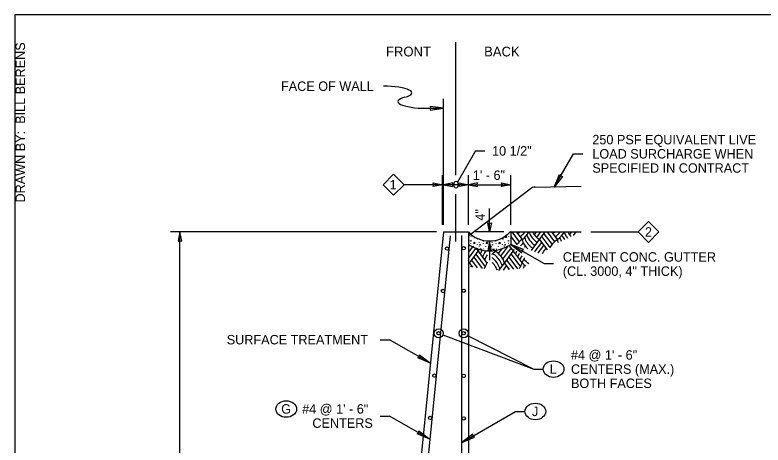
# Model space of a CAD drawing. Extents: x 99862 to 103151, y 100000 to 105076.
# Drawn here: x 99862 to 101127, y 101348 to 102076 of the extents above; entities that cross this region are included whole.
import ezdxf

# ---------------------------------------------------------------- set-up
doc = ezdxf.new("R2010")
doc.units = 0
for name, color, linetype in [('Level 1', 7, 'Continuous'), ('Level 10', 7, 'Continuous'), ('Level 13', 7, 'Continuous'), ('Level 15', 7, 'Continuous'), ('Level 2', 7, 'Continuous'), ('Level 20', 7, 'Continuous'), ('Level 22', 7, 'Continuous'), ('Level 5', 7, 'Continuous'), ('Level 62', 7, 'Continuous')]:
    doc.layers.add(name, color=color, linetype=linetype)

msp = doc.modelspace()

# ---------------------------------------------------------------- linework, layer by layer
at = {"layer": 'Level 1'}
msp.add_lwpolyline([(99862, 99999.5), (103151, 99999.5), (103151, 102075.5), (99862, 102075.5)], close=True, dxfattribs=at)
at = {"layer": 'Level 10'}
for p, q in [((100586.9, 101708.3), (100495.4, 100796.3)), ((100586.9, 101708.3), (100628.9, 101708.3)), ((100628.9, 101708.3), (100628.9, 100796.3)), ((100633.6, 101700.1), (100633.8, 101700.5)), ((100639.2, 101697.2), (100639.3, 101697)), ((100697.4, 101700.1), (100697.6, 101700.5)), ((100700.9, 101707.3), (100700.9, 101687.2)), ((100633.2, 101688.8), (100633.3, 101689.2)), ((100643.7, 101687.7), (100643.8, 101687.3)), ((100647.7, 101690.6), (100647.9, 101691)), ((100654.4, 101688.8), (100654.6, 101689.2)), ((100665, 101687.7), (100665, 101687.3)), ((100669, 101690.6), (100669.1, 101691)), ((100675.7, 101688.8), (100675.9, 101689.2)), ((100686.3, 101687.7), (100686.3, 101687.3)), ((100690.2, 101690.6), (100690.4, 101691)), ((100697, 101688.8), (100697.2, 101689.2)), ((100637.2, 101683.6), (100637.4, 101684)), ((100644.1, 101680.4), (100644.3, 101680.8)), ((100646.8, 101683.6), (100646.9, 101683.4)), ((100646.9, 101683.5), (100647.1, 101683.3)), ((100654.9, 101679.3), (100655.1, 101679.7)), ((100658.5, 101683.6), (100658.7, 101684)), ((100660.4, 101676.5), (100660.5, 101676.4)), ((100665.4, 101680.4), (100665.6, 101680.8)), ((100668, 101683.6), (100668.2, 101683.4)), ((100668.2, 101683.5), (100668.4, 101683.3)), ((100676.1, 101679.3), (100676.3, 101679.7)), ((100679.7, 101683.6), (100679.9, 101684)), ((100686.7, 101680.4), (100686.8, 101680.8)), ((100689.3, 101683.6), (100689.5, 101683.4)), ((100689.5, 101683.5), (100689.6, 101683.3))]:
    msp.add_line(p, q, dxfattribs=at)
for points in [[(100686.4, 101696.1), (100686.9, 101697.2), (100687.8, 101696.5), (100686.4, 101696.1)], [(100691.4, 101698.9), (100692.5, 101700.9)], [(100692.7, 101701), (100693.6, 101699.1), (100691.5, 101698.9)], [(100632.3, 101692.9), (100632.8, 101694), (100633.7, 101693.3), (100632.3, 101692.9)], [(100638.6, 101688.3), (100638.9, 101690.9), (100640.5, 101689.2), (100638.6, 101688.4)], [(100643.8, 101696.1), (100644.2, 101696.9)], [(100645.1, 101696.5), (100643.8, 101696.1)], [(100647.8, 101686), (100648.3, 101687.1), (100649.2, 101686.4), (100647.8, 101686)], [(100654.7, 101693.5), (100655, 101693.3), (100653.6, 101692.9)], [(100653.6, 101692.9), (100653.9, 101693.5)], [(100659.8, 101688.3), (100660.2, 101690.9), (100661.8, 101689.2), (100659.9, 101688.4)], [(100669, 101686), (100669.6, 101687.1), (100670.5, 101686.4), (100669, 101686)], [(100676, 101693.5), (100676.2, 101693.3), (100674.8, 101692.9)], [(100674.8, 101692.9), (100675, 101693.3)], [(100681.1, 101688.3), (100681.5, 101690.9), (100683, 101689.2), (100681.1, 101688.4)], [(100690.3, 101686), (100690.8, 101687.1), (100691.7, 101686.4), (100690.3, 101686)], [(100696.1, 101692.9), (100696.6, 101694), (100697.5, 101693.3), (100696.1, 101692.9)], [(100649, 101678.4), (100650.1, 101680.4), (100651, 101678.3), (100649.5, 101678.2)], [(100670.2, 101678.1), (100671.4, 101680.4), (100672.3, 101678.3), (100670.2, 101678.1)]]:
    msp.add_lwpolyline(points, dxfattribs=at)
for centre, radius, start, end in [((100664.2, 101741.5), 48.5, 223.301, 316.2231), ((100699.9, 101707.3), 1, 0, 134.9971), ((100664.9, 101740.8), 64.5, 236.0728, 303.9272)]:
    msp.add_arc(centre, radius, start, end, dxfattribs=at)
at = {"layer": 'Level 13'}
for p, q in [((100598.2, 101701.7), (100517.4, 100896.3)), ((100618, 100957.3), (100618, 101702.3))]:
    msp.add_line(p, q, dxfattribs=at)
at = {"layer": 'Level 15'}
for p, q in [((100607.9, 101804.3), (100607.9, 102029.5)), ((100586.9, 101720.3), (100586.9, 101933.5)), ((100558, 101917.5), (100586.9, 101917.5)), ((100641, 101845.5), (100610.3, 101792.5)), ((100641, 101845.5), (100657, 101845.5)), ((100774, 101784.1), (100806.5, 101840.4)), ((100806.5, 101840.4), (100822.5, 101840.4)), ((100584.9, 101720.3), (100584.9, 101804.3)), ((100628.9, 101720.3), (100628.9, 101804.3)), ((100700.9, 101720.3), (100700.9, 101804.3)), ((100584.9, 101788.3), (100520.1, 101788.3)), ((100628.9, 101788.3), (100586.9, 101788.3)), ((100628.9, 101788.3), (100700.9, 101788.3)), ((100607.9, 101692.3), (100607.9, 101772.3)), ((100664.9, 101708.3), (100664.9, 101747.9)), ((100574.9, 101708.3), (100124.9, 101708.3)), ((100140.9, 101220.3), (100140.9, 101708.3)), ((100688.9, 101708.3), (100640.9, 101708.3)), ((100836, 101708.3), (100916, 101708.3)), ((100664.9, 101692.3), (100664.9, 101660.3)), ((100700.9, 101687.2), (100757.2, 101654.7)), ((100757.2, 101654.7), (100773.2, 101654.7)), ((100585.6, 101534.2), (100739.5, 101476.2)), ((100627.7, 101533.3), (100739.5, 101476.2)), ((100479.8, 101526), (100495.8, 101526)), ((100564.6, 101486.2), (100495.8, 101526)), ((100739.5, 101476.2), (100755.5, 101476.2)), ((100479.8, 101396.7), (100495.8, 101396.7)), ((100563.6, 101357.5), (100495.8, 101396.7)), ((100618, 101352.1), (100708.7, 101404.5)), ((100708.7, 101404.5), (100724.7, 101404.5))]:
    msp.add_line(p, q, dxfattribs=at)
for points in [[(100586.9, 101917.5), (100564.1, 101920.5), (100565.1, 101917.5), (100564.1, 101914.6)], [(100774, 101784.1), (100782.9, 101805.4), (100784.9, 101803), (100788, 101802.4)], [(100584.9, 101788.3), (100569.2, 101785.2), (100569.9, 101788.3), (100569.2, 101791.3)], [(100586.9, 101788.3), (100602.6, 101785.2), (100601.9, 101788.3), (100602.6, 101791.3)], [(100628.9, 101788.3), (100613.2, 101785.2), (100613.9, 101788.3), (100613.2, 101791.3)], [(100628.9, 101788.3), (100644.6, 101785.2), (100643.9, 101788.3), (100644.6, 101791.3)], [(100700.9, 101788.3), (100685.2, 101785.2), (100685.9, 101788.3), (100685.2, 101791.3)], [(100664.9, 101708.3), (100661.8, 101724), (100664.9, 101723.3), (100668, 101724)], [(100140.9, 101708.3), (100137.8, 101692.5), (100140.9, 101693.3), (100144, 101692.5)], [(100664.9, 101692.3), (100661.8, 101676.5), (100664.9, 101677.3), (100668, 101676.5)], [(100700.9, 101687.2), (100719.2, 101673.2), (100719.7, 101676.3), (100722.1, 101678.4)], [(100564.6, 101486.2), (100543.3, 101495.1), (100545.8, 101497.1), (100546.3, 101500.2)], [(100563.6, 101357.5), (100542.4, 101366.4), (100544.8, 101368.4), (100545.4, 101371.5)], [(100618, 101352.1), (100639.3, 101361), (100636.9, 101363), (100636.3, 101366.1)]]:
    msp.add_lwpolyline(points, close=True, dxfattribs=at)
for centre in [(100578.6, 101536.8), (100621, 101536.8)]:
    msp.add_circle(centre, 7.5, dxfattribs=at)
for centre, start_param, end_param in [((100485.2, 101943.7), 5.569461, 7.853982), ((100558, 101928.9), 2.427868, 4.712389)]:
    msp.add_ellipse(centre, major_axis=(48.2, 0), ratio=0.234933, start_param=start_param, end_param=end_param, dxfattribs=at)
msp.add_ellipse((100607.9, 101788.3), major_axis=(0, -6), ratio=0.57735, dxfattribs=at)
at = {"layer": 'Level 2'}
for p, q in [((100699.9, 101708.3), (100820, 101708.3)), ((100700.9, 101700.6), (100711, 101687.1)), ((100702.6, 101708.3), (100715, 101691.6)), ((100710, 101708.3), (100719.7, 101695.3)), ((100740.7, 101703.4), (100744.3, 101708.3)), ((100744.7, 101699), (100751.7, 101708.3)), ((100749.4, 101695.3), (100759.1, 101708.3)), ((100753.1, 101700.2), (100766.9, 101681.8)), ((100756.8, 101705.2), (100770.4, 101687.1)), ((100762, 101708.3), (100774.4, 101691.6)), ((100769.4, 101708.3), (100779.1, 101695.3)), ((100800.1, 101703.4), (100803.7, 101708.3)), ((100806.5, 101702.1), (100811.1, 101708.3)), ((100817.7, 101707.2), (100818.5, 101708.3)), ((100628.9, 101683.1), (100631, 101685.9)), ((100690, 101675.5), (100697, 101684.8)), ((100735.8, 101677.1), (100749.4, 101695.3)), ((100742, 101675.5), (100753.1, 101690.3)), ((100749.4, 101695.3), (100762.2, 101678.2)), ((100749.4, 101675.5), (100756.8, 101685.4)), ((100628.9, 101673.2), (100630.6, 101675.5)), ((100628.9, 101663.3), (100638, 101675.5)), ((100630.6, 101675.5), (100636.4, 101683.2)), ((100630.6, 101655.7), (100645.5, 101675.5)), ((100638, 101675.5), (100641.7, 101680.4)), ((100641, 101681.5), (100645.5, 101675.5)), ((100645.5, 101675.5), (100660.3, 101655.7)), ((100675.2, 101675.5), (100677, 101678)), ((100679.8, 101671.8), (100682.6, 101675.5)), ((100682.6, 101675.5), (100685.9, 101679.9)), ((100683.9, 101667.3), (100690, 101675.5)), ((100687.3, 101662), (100697.4, 101675.5)), ((100690, 101655.7), (100704.9, 101675.5)), ((100697.4, 101675.5), (100701.1, 101680.4)), ((100698.4, 101684.1), (100704.9, 101675.5)), ((100704.9, 101675.5), (100719.7, 101655.7)), ((100741.4, 101674.7), (100742, 101675.5)), ((100747.1, 101672.4), (100749.4, 101675.5)), ((100754.2, 101672), (100756.8, 101675.5)), ((100756.8, 101675.5), (100760.5, 101680.4)), ((100634.3, 101660.6), (100644, 101647.7)), ((100638, 101665.6), (100652.2, 101646.7)), ((100641.7, 101670.5), (100657.6, 101649.4)), ((100693.7, 101660.6), (100705.1, 101645.4)), ((100697.4, 101665.6), (100712.1, 101646)), ((100701.1, 101670.5), (100717, 101649.4)), ((100628.9, 101653.4), (100630.6, 101655.7)), ((100630.6, 101655.7), (100635.8, 101648.7)), ((100633.1, 101649.1), (100634.3, 101650.7)), ((100680.7, 101643.2), (100690, 101655.7)), ((100688.6, 101643.9), (100693.7, 101650.7)), ((100690, 101655.7), (100698.2, 101644.8)), ((100696.6, 101644.6), (100697.4, 101645.8))]:
    msp.add_line(p, q, dxfattribs=at)
for centre, start, end in [((100691.3, 101736.4), 303.9036, 311.5466), ((100695, 101731.4), 303.9036, 321.9248), ((100698.7, 101726.5), 303.9036, 330.9892), ((100759.2, 101711.6), 200.2432, 228.9599), ((100762.9, 101716.6), 201.4344, 220.9416), ((100766.6, 101721.5), 200.8778, 211.332), ((100766.6, 101721.5), 211.3319, 236.0964), ((100770.4, 101726.5), 209.0108, 236.0964), ((100750.7, 101736.4), 303.9036, 311.5466), ((100754.4, 101731.4), 303.9036, 321.9248), ((100758.1, 101726.5), 303.9036, 330.9892), ((100818.6, 101711.6), 200.2432, 209.9804), ((100822.3, 101716.6), 201.4344, 214.5616), ((100826, 101721.5), 200.8778, 211.332), ((100826, 101721.5), 211.3319, 219.2089), ((100829.8, 101726.5), 209.0108, 223.9593), ((100740.7, 101664.1), 123.9036, 141.8404), ((100744.4, 101659.2), 126.3063, 136.7886), ((100755.5, 101706.7), 197.6434, 225.7148), ((100762.9, 101716.6), 220.9415, 236.0964), ((100800.1, 101664.1), 123.9036, 151.826), ((100814.9, 101706.7), 197.6434, 205.4349), ((100681.3, 101664.1), 156.2156, 162.3566), ((100685, 101659.2), 154.2265, 162.3566), ((100685, 101659.2), 150.417, 154.2266), ((100688.7, 101654.2), 145.491, 162.3566), ((100688.7, 101654.2), 142.4063, 145.4911), ((100696.1, 101644.3), 123.9036, 136.4335), ((100696.1, 101706.7), 231.6282, 236.0964), ((100654.2, 101644.3), 17.6434, 56.0963), ((100740.7, 101664.1), 157.7004, 162.3566), ((100744.4, 101659.2), 154.2265, 162.3566), ((100748.1, 101654.2), 127.1006, 131.5623), ((100759.2, 101711.6), 228.9599, 236.0964), ((100594.8, 101644.3), 17.6434, 24.8779), ((100692.4, 101649.3), 147.0008, 162.3566), ((100646.8, 101634.4), 40.9413, 53.9422), ((100650.5, 101639.4), 48.9597, 58.5465), ((100650.5, 101639.4), 17.6434, 48.9597), ((100748.1, 101654.2), 152.4732, 162.3566), ((100751.8, 101649.3), 149.8941, 162.3566), ((100755.5, 101644.3), 147.3298, 162.3566), ((100702.5, 101629.5), 40.8248, 58.4874), ((100624.5, 101667.1), 326.2709, 342.3566), ((100696.1, 101644.3), 159.6308, 162.3566), ((100643.1, 101629.5), 31.3316, 46.576), ((100646.8, 101634.4), 17.6434, 40.9414), ((100643.1, 101629.5), 21.8561, 31.3317), ((100683.9, 101667.1), 326.4195, 342.3566), ((100698.7, 101624.5), 43.348, 56.0964), ((100687.6, 101662.1), 336.651, 345.0113)]:
    msp.add_arc(centre, 37.6, start, end, dxfattribs=at)
at = {"layer": 'Level 20'}
for points in [[(100502.5, 101805.8), (100520.1, 101788.3), (100502.5, 101770.7), (100485, 101788.3)], [(100933.6, 101725.8), (100951.2, 101708.3), (100933.6, 101690.7), (100916, 101708.3)]]:
    msp.add_lwpolyline(points, close=True, dxfattribs=at)
for centre in [(100773, 101476.2), (100320.8, 101408.6), (100742.2, 101404.5)]:
    msp.add_ellipse(centre, major_axis=(-17.5, 0), ratio=0.8, dxfattribs=at)
at = {"layer": 'Level 22'}
for centre in [(100592.9, 101680.1), (100621, 101680.8), (100585.8, 101608.4), (100621, 101608.8), (100578.6, 101536.8), (100621, 101536.8), (100571.4, 101465.2), (100621, 101464.8), (100564.2, 101393.5), (100621, 101392.8)]:
    msp.add_circle(centre, 2.85, dxfattribs=at)
at = {"layer": 'Level 5'}
for p, q in [((100742, 101784.1), (100819.9, 101785.9)), ((100629.5, 101702.4), (100733.6, 101781.2))]:
    msp.add_line(p, q, dxfattribs=at)
msp.add_arc((100742.3, 101769.7), 14.5, 91.2659, 127.1192, dxfattribs=at)

# ---------------------------------------------------------------- texts
at = {"layer": 'Level 20'}
for s, height, p in [('FRONT', 16.5, (100489.6, 102005.3)), ('BACK', 16.5, (100655.6, 102005.3)), ('250 PSF EQUIVALENT LIVE', 16, (100838.6, 101856.5)), ('10 1/2"', 16, (100669, 101837.5)), ('LOAD SURCHARGE WHEN', 16, (100838.6, 101832.5)), ('SPECIFIED IN CONTRACT', 16, (100838.6, 101808.5)), ('1\' - 6"', 16, (100636.5, 101796.3)), ('1', 16, (100495.6, 101780.3)), ('2', 16, (100927.6, 101700.3)), ('CEMENT CONC. GUTTER', 16, (100788.7, 101658)), ('(CL. 3000, 4" THICK)', 16, (100788.7, 101634)), ('SURFACE TREATMENT', 16, (100220.2, 101518)), ('#4 @ 1\' - 6"', 16, (100802.5, 101492.2)), ('L', 16, (100766.6, 101468.3)), ('CENTERS (MAX.)', 16, (100802.5, 101468.2)), ('BOTH FACES', 16, (100802.5, 101444.2)), ('G', 16, (100312.3, 101400.8)), ('  #4 @ 1\' - 6"', 16, (100335.9, 101400.8)), ('J', 16, (100736.5, 101396.7)), ('CENTERS', 16, (100365.1, 101376.8))]:
    msp.add_text(s, height=height, dxfattribs=at).set_placement(p)
for s, rotation, p in [('FACE OF WALL', 360, (100312, 101947)), ('4"', 90, (100656.9, 101727.3))]:
    msp.add_text(s, height=16, rotation=rotation, dxfattribs=at).set_placement(p)
at = {"layer": 'Level 62'}
msp.add_text('DRAWN BY:  BILL BERENS', height=16, rotation=90, dxfattribs=at).set_placement((99879, 101758.1))

doc.saveas('drawing.dxf')
